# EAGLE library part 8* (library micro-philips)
CMOS single-chip 8-bit Microcontroller 80C31/32 pin compatible
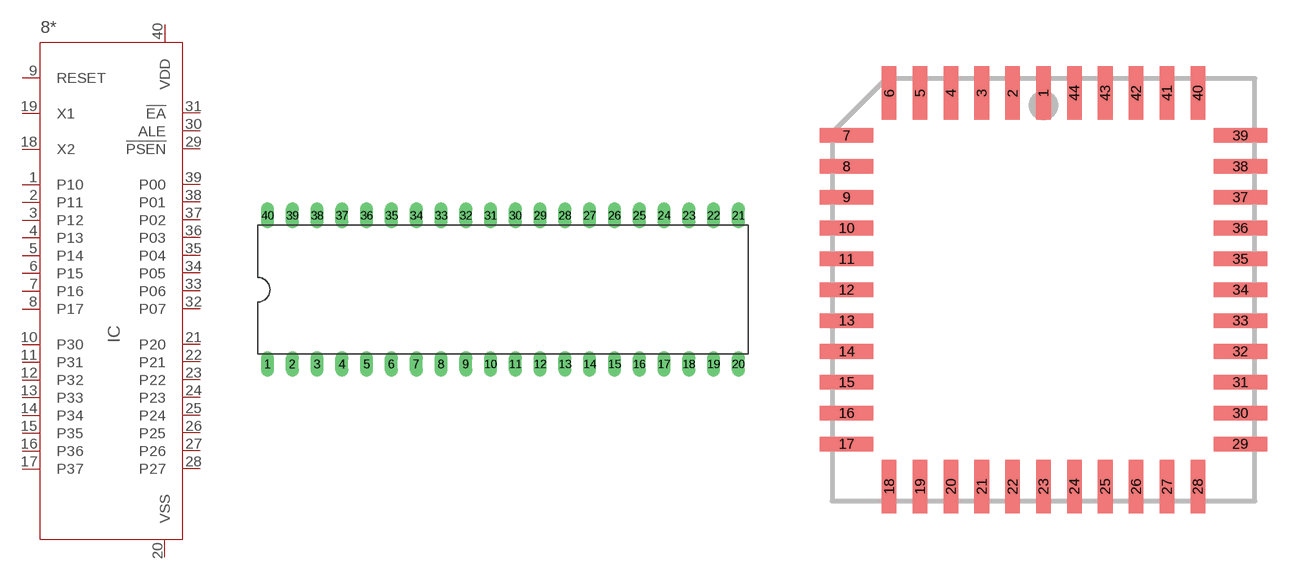
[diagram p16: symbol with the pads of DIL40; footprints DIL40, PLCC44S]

Designator prefix IC

## 80C31SBPN (MF: FARNELL; MPN: P80C31SBPN; OC_FARNELL: 120509; OC_NEWARK: 67C9971), 80C31SFPN (MF: FARNELL; MPN: P80C31SBPN; OC_FARNELL: 120509; OC_NEWARK: 67C9971), 80C32SBPN (MF: FARNELL; MPN: P80C32SBPN; OC_FARNELL: 121071; OC_NEWARK: 67C9973), 80C32SFPN (MF: FARNELL; MPN: P80C32SBPN; OC_FARNELL: 121071; OC_NEWARK: 67C9973), 80C32UBPN (OC_FARNELL: unknown; OC_NEWARK: unknown), 80C32UFPN (OC_FARNELL: unknown; OC_NEWARK: unknown), 80C652PN (OC_FARNELL: unknown; OC_NEWARK: unknown), 83C652PN (OC_FARNELL: unknown; OC_NEWARK: unknown)  [DIL40]
1  P10
2  P11
3  P12
4  P13
5  P14
6  P15
7  P16
8  P17
9  RESET
10  P30
11  P31
12  P32
13  P33
14  P34
15  P35
16  P36
17  P37
18  X2  out
19  X1  in
20  VSS  pwr
21  P20
22  P21
23  P22
24  P23
25  P24
26  P25
27  P26
28  P27
29  !PSEN  out
30  ALE  out
31  !EA  in
32  P07
33  P06
34  P05
35  P04
36  P03
37  P02
38  P01
39  P00
40  VDD  pwr

## 80C31SBAA (MPN: P80C31SBAA,512; OC_FARNELL: 1831226; OC_NEWARK: 70R8431), 80C31SFAA (OC_FARNELL: unknown; OC_NEWARK: unknown), 80C32SBAA (MPN: P80C32SBAA,512; OC_FARNELL: 1831229; OC_NEWARK: 70R8434), 80C32SFAA (OC_FARNELL: 1831229; OC_NEWARK: unknown), 80C32UBAA (MPN: P80C32UBAA; OC_FARNELL: 1201265; OC_NEWARK: 24M6583), 80C32UFAA (MPN: P80C32UFAA,512; OC_FARNELL: unknown; OC_NEWARK: 70R8437)  [PLCC44S]
2  P10
3  P11
4  P12
5  P13
6  P14
7  P15
8  P16
9  P17
10  RESET
11  P30
13  P31
14  P32
15  P33
16  P34
17  P35
18  P36
19  P37
20  X2  out
21  X1  in
22  VSS  pwr
24  P20
25  P21
26  P22
27  P23
28  P24
29  P25
30  P26
31  P27
32  !PSEN  out
33  ALE  out
35  !EA  in
36  P07
37  P06
38  P05
39  P04
40  P03
41  P02
42  P01
43  P00
44  VDD  pwr

## 80C31SBBB (MPN: P80C31SBBB,557; OC_FARNELL: unknown; OC_NEWARK: 70R8432), 80C31SFBB (OC_FARNELL: unknown; OC_NEWARK: unknown), 80C32SBBB (OC_FARNELL: unknown; OC_NEWARK: unknown), 80C32SFBB (OC_FARNELL: unknown; OC_NEWARK: unknown), 80C32UBBB (OC_FARNELL: unknown; OC_NEWARK: unknown), 80C32UFBB (MPN: P80C32UFBB,557; OC_FARNELL: unknown; OC_NEWARK: 70R8438)  [QFP44_SOT307-2]
1  P15
2  P16
3  P17
4  RESET
5  P30
7  P31
8  P32
9  P33
10  P34
11  P35
12  P36
13  P37
14  X2  out
15  X1  in
16  VSS  pwr
18  P20
19  P21
20  P22
21  P23
22  P24
23  P25
24  P26
25  P27
26  !PSEN  out
27  ALE  out
29  !EA  in
30  P07
31  P06
32  P05
33  P04
34  P03
35  P02
36  P01
37  P00
38  VDD  pwr
40  P10
41  P11
42  P12
43  P13
44  P14

## Footprint DIL40 (pad centres in mm)
Dual In Line
drill 0.813 long: 1 -24.13,-7.62; 2 -21.59,-7.62; 3 -19.05,-7.62; 4 -16.51,-7.62; 5 -13.97,-7.62; 6 -11.43,-7.62; 7 -8.89,-7.62; 8 -6.35,-7.62; 9 -3.81,-7.62; 10 -1.27,-7.62; 11 1.27,-7.62; 12 3.81,-7.62; 13 6.35,-7.62; 14 8.89,-7.62; 15 11.43,-7.62; 16 13.97,-7.62; 17 16.51,-7.62; 18 19.05,-7.62; 19 21.59,-7.62; 20 24.13,-7.62; 21 24.13,7.62; 22 21.59,7.62; 23 19.05,7.62; 24 16.51,7.62; 25 13.97,7.62; 26 11.43,7.62; 27 8.89,7.62; 28 6.35,7.62; 29 3.81,7.62; 30 1.27,7.62; 31 -1.27,7.62; 32 -3.81,7.62; 33 -6.35,7.62; 34 -8.89,7.62; 35 -11.43,7.62; 36 -13.97,7.62; 37 -16.51,7.62; 38 -19.05,7.62; 39 -21.59,7.62; 40 -24.13,7.62

## Footprint PLCC44S (pad centres in mm)
PLASTIC LEADED CHIP CARRIER square
smd 0.6 x 2.2: 1 0,8.1; 2 -1.27,8.1; 3 -2.54,8.1; 4 -3.81,8.1; 5 -5.08,8.1; 6 -6.35,8.1; 18 -6.35,-8.1; 19 -5.08,-8.1; 20 -3.81,-8.1; 21 -2.54,-8.1; 22 -1.27,-8.1; 23 0,-8.1; 24 1.27,-8.1; 25 2.54,-8.1; 26 3.81,-8.1; 27 5.08,-8.1; 28 6.35,-8.1; 40 6.35,8.1; 41 5.08,8.1; 42 3.81,8.1; 43 2.54,8.1; 44 1.27,8.1
smd 2.2 x 0.6: 7 -8.1,6.35; 8 -8.1,5.08; 9 -8.1,3.81; 10 -8.1,2.54; 11 -8.1,1.27; 12 -8.1,0; 13 -8.1,-1.27; 14 -8.1,-2.54; 15 -8.1,-3.81; 16 -8.1,-5.08; 17 -8.1,-6.35; 29 8.1,-6.35; 30 8.1,-5.08; 31 8.1,-3.81; 32 8.1,-2.54; 33 8.1,-1.27; 34 8.1,0; 35 8.1,1.27; 36 8.1,2.54; 37 8.1,3.81; 38 8.1,5.08; 39 8.1,6.35

## Footprint QFP44_SOT307-2 (pad centres in mm)
Plastic Quad Flat Package SOT307-2 44 leads (lead length 1.3 mm); body 10 x 10 x 1.75 mm SOT307-2 source: http://www.semiconductors.philips.com/ LQFP-MSQFP-QFP-SQFP-TQFP-REFLOW.pdf
smd 0.5 x 1.8: 1 -4,-6; 2 -3.2,-6; 3 -2.4,-6; 4 -1.6,-6; 5 -0.8,-6; 6 0,-6; 7 0.8,-6; 8 1.6,-6; 9 2.4,-6; 10 3.2,-6; 11 4,-6; 23 4,6; 24 3.2,6; 25 2.4,6; 26 1.6,6; 27 0.8,6; 28 0,6; 29 -0.8,6; 30 -1.6,6; 31 -2.4,6; 32 -3.2,6; 33 -4,6
smd 1.8 x 0.5: 12 6,-4; 13 6,-3.2; 14 6,-2.4; 15 6,-1.6; 16 6,-0.8; 17 6,0; 18 6,0.8; 19 6,1.6; 20 6,2.4; 21 6,3.2; 22 6,4; 34 -6,4; 35 -6,3.2; 36 -6,2.4; 37 -6,1.6; 38 -6,0.8; 39 -6,0; 40 -6,-0.8; 41 -6,-1.6; 42 -6,-2.4; 43 -6,-3.2; 44 -6,-4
